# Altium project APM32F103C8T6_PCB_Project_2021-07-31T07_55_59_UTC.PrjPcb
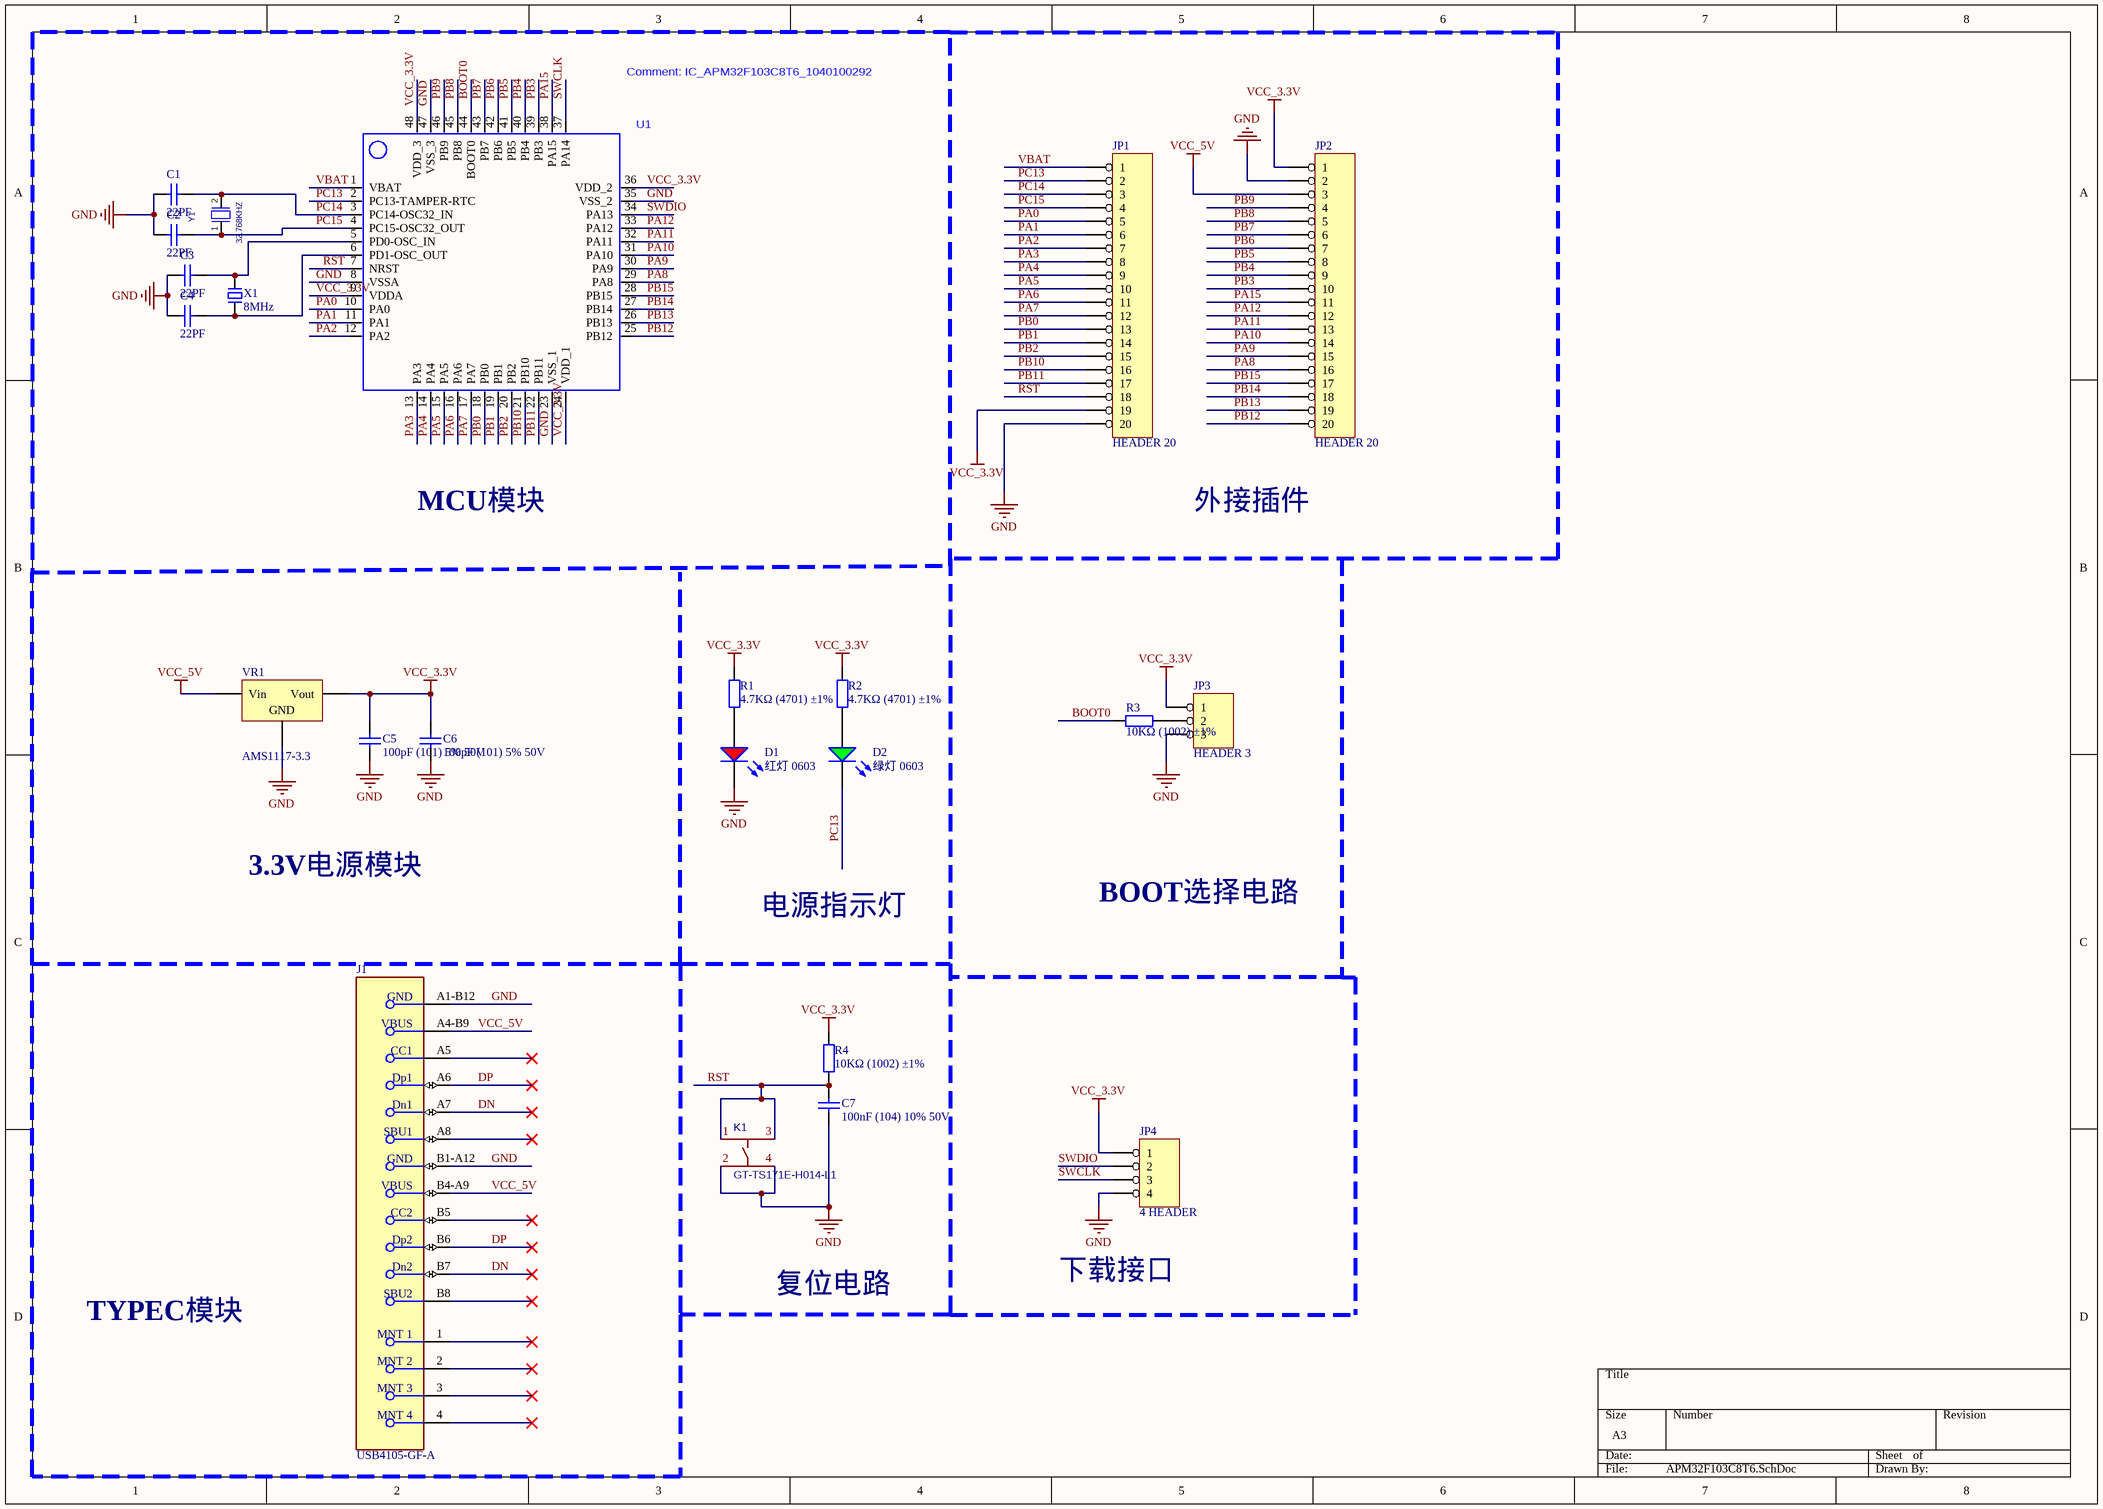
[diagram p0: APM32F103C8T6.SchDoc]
1 sheet, 23 parts. Net scope: global (net labels, ports and power ports of the same name join across sheets).
Board file: APM32F103C856.PcbDoc

## Sheet APM32F103C8T6.SchDoc
size A3; SheetNumber: 1; SheetTotal: 1

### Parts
C1  22PF  [0603_C]
C2  22PF  [0603_C]
C3  22PF  [0603_C]
C4  22PF  [0603_C]
C5  100pF (101) 5% 50V  [0603_C]
C6  100pF (101) 5% 50V  [0603_C]
C7  100nF (104) 10% 50V  [0603_C]
D1  红灯 0603  [0603_LED_S1]
D2  绿灯 0603  [0603_LED_S1]
J1  USB4105-GF-A  [FP-USB4105-GF-A-MFG]
JP1  HEADER 20  [HDR1X20]
JP2  HEADER 20  [HDR1X20]
JP3  HEADER 3  [HDR1X3]
JP4  4 HEADER  [HDR1X4]
K1  GT-TS171E-H014-L1  [SW-SMD_4P-L3.0-W2.8-P1.65-TL_GT-TS171A-H014-L1]
R1  4.7KΩ (4701) ±1%  [0603_R]
R2  4.7KΩ (4701) ±1%  [0603_R]
R3  10KΩ (1002) ±1%  [0603_R]
R4  10KΩ (1002) ±1%  [0603_R]
U1  IC_APM32F103C8T6_1040100292  [LQFP48]
VR1  AMS1117-3.3  [SOT-223]
X1  8MHz  [OSC HC-49S]
Y1  value 32.768KHZ  [3215]  (hidden comment: CRYSTAL)

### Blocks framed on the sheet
MCU模块: C1-C4 U1 X1 Y1

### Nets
GND: C1.2 C2.2 C3.2 C4.2 C5.1 C6.2 C7.2 D1.K J1.A1-B12(GND) J1.B1-A12(GND) JP1.20 JP2.2 JP3.3 JP4.4 K1.2 K1.4 U1.8(VSSA) U1.23(VSS_1) U1.35(VSS_2) U1.47(VSS_3) VR1.1(GND)
VCC_3.3V: C5.2 C6.1 JP1.19 JP2.1 JP3.1 JP4.1 R1.2 R2.2 R4.2 U1.9(VDDA) U1.24(VDD_1) U1.36(VDD_2) U1.48(VDD_3) VR1.2(Vout)
VCC_5V: J1.A4-B9(VBUS) J1.B4-A9(VBUS) JP2.3 VR1.3(Vin)
BOOT0: R3.1 U1.44(BOOT0)
DN: J1.A7(Dn1) J1.B7(Dn2)
DP: J1.A6(Dp1) J1.B6(Dp2)
PA0: JP1.5 U1.10(PA0)
PA1: JP1.6 U1.11(PA1)
PA2: JP1.7 U1.12(PA2)
PA3: JP1.8 U1.13(PA3)
PA4: JP1.9 U1.14(PA4)
PA5: JP1.10 U1.15(PA5)
PA6: JP1.11 U1.16(PA6)
PA7: JP1.12 U1.17(PA7)
PA8: JP2.16 U1.29(PA8)
PA9: JP2.15 U1.30(PA9)
PA10: JP2.14 U1.31(PA10)
PA11: JP2.13 U1.32(PA11)
PA12: JP2.12 U1.33(PA12)
PA15: JP2.11 U1.38(PA15)
PB0: JP1.13 U1.18(PB0)
PB1: JP1.14 U1.19(PB1)
PB2: JP1.15 U1.20(PB2)
PB3: JP2.10 U1.39(PB3)
PB4: JP2.9 U1.40(PB4)
PB5: JP2.8 U1.41(PB5)
PB6: JP2.7 U1.42(PB6)
PB7: JP2.6 U1.43(PB7)
PB8: JP2.5 U1.45(PB8)
PB9: JP2.4 U1.46(PB9)
PB10: JP1.16 U1.21(PB10)
PB11: JP1.17 U1.22(PB11)
PB12: JP2.20 U1.25(PB12)
PB13: JP2.19 U1.26(PB13)
PB14: JP2.18 U1.27(PB14)
PB15: JP2.17 U1.28(PB15)
PC13: D2.K JP1.2 U1.2(PC13-TAMPER-RTC)
PC14: C1.1 JP1.3 U1.3(PC14-OSC32_IN) Y1.2
PC15: C2.1 JP1.4 U1.4(PC15-OSC32_OUT) Y1.1
RST: C7.1 JP1.18 K1.1 K1.3 R4.1 U1.7(NRST)
SWCLK: JP4.3 U1.37(PA14)
SWDIO: JP4.2 U1.34(PA13)
VBAT: JP1.1 U1.1(VBAT)
NetC3_1: C3.1 U1.5(PD0-OSC_IN) X1.2
NetC4_1: C4.1 U1.6(PD1-OSC_OUT) X1.1
NetD1_A: D1.A R1.1
NetD2_A: D2.A R2.1
NetJP3_2: JP3.2 R3.2

Not connected (* = marked no-connect by the designer): J1 1(MNT_1)* 2(MNT_2)* 3(MNT_3)* 4(MNT_4)* A5(CC1)* A8(SBU1)* B5(CC2)* B8(SBU2)*

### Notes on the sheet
- 外接插件
- 3.3V电源模块
- 电源指示灯
- BOOT选择电路
- TYPEC模块
- 复位电路
- 下载接口

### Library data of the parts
C1-C6 = 0603 100pF (101) 5% 50V: 贴片电容
C7 = 0603 100nF (104) 10% 50V: 贴片电容
D1 = 0603 红灯: 发光二极管
D2 = 0603 绿灯: 发光二极管
J1 = CMP-245163-000001-1: CONN RCPT USB2.0 TYPEC 5A; Manufacturer: GCT; Voltage Rating: 20V; Is Female: yes; Current Rating: 5/6.25/1.25/0.25A; Number Of Contacts: 16; Conn Orientation: Right Angle
JP4 = 4 HEADER: 4 Pin Header
K1 = GT-TS171E-H014-L1: BOM_Manufacturer: G-Switch; Contributor: LCSC
R1 R2 = 0603 4.7KΩ (4701) 1%: 贴片电阻
R3 R4 = 0603 10KΩ (1002) 1%: 贴片电阻
VR1 = SOT-223 AMS1117-3.3: 低压差线性稳压(LDO)
X1 = XTAL-2P: 2脚无源脚晶振; 版权归属: 源创客
Y1 = CRYSTAL: XTAL 32.768KHZ 7PF 20PPM -- SMT; CAD_APPROVED: Yes; MFG_PN01: FC-135 32.7680KA-AG3; MFG_NAME01: EPSON ELECTRONICS; AGILE_PN: 230-78102; Source_Path: Q:\ORCADCIS\SYMBOLS\FCL_XTAL_OSC.OLB; CLASS: IC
